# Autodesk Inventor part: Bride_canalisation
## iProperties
Shininess: 64.0
Length Units: 11269
Angle Units: 11279
Time Units: 11290
Mass Units: 11283
Length Display Precision: 3
Angle Display Precision: 2
Compacted: True
Part Number: Bride_canalisation
Document SubType Name: Modeling
Created: 2008-02
Material: Acier inoxydable, austénitique
Designer: Pascal
Density: 8.03 g/cm^3
Density: 0.0
Volumn: 0.0
Area: 0.0
PropertySet Name: Model Information
Control State: 0
Master: False
Checked Out: False
DESIGNATION: pièce
Author: Pascal
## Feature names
1. Extrusion1
2. Extrusion2
3. Réseau rectangulaire1 [Rectangular Pattern]
4. Extrusion3
5. Réseau rectangulaire2 [Rectangular Pattern]
